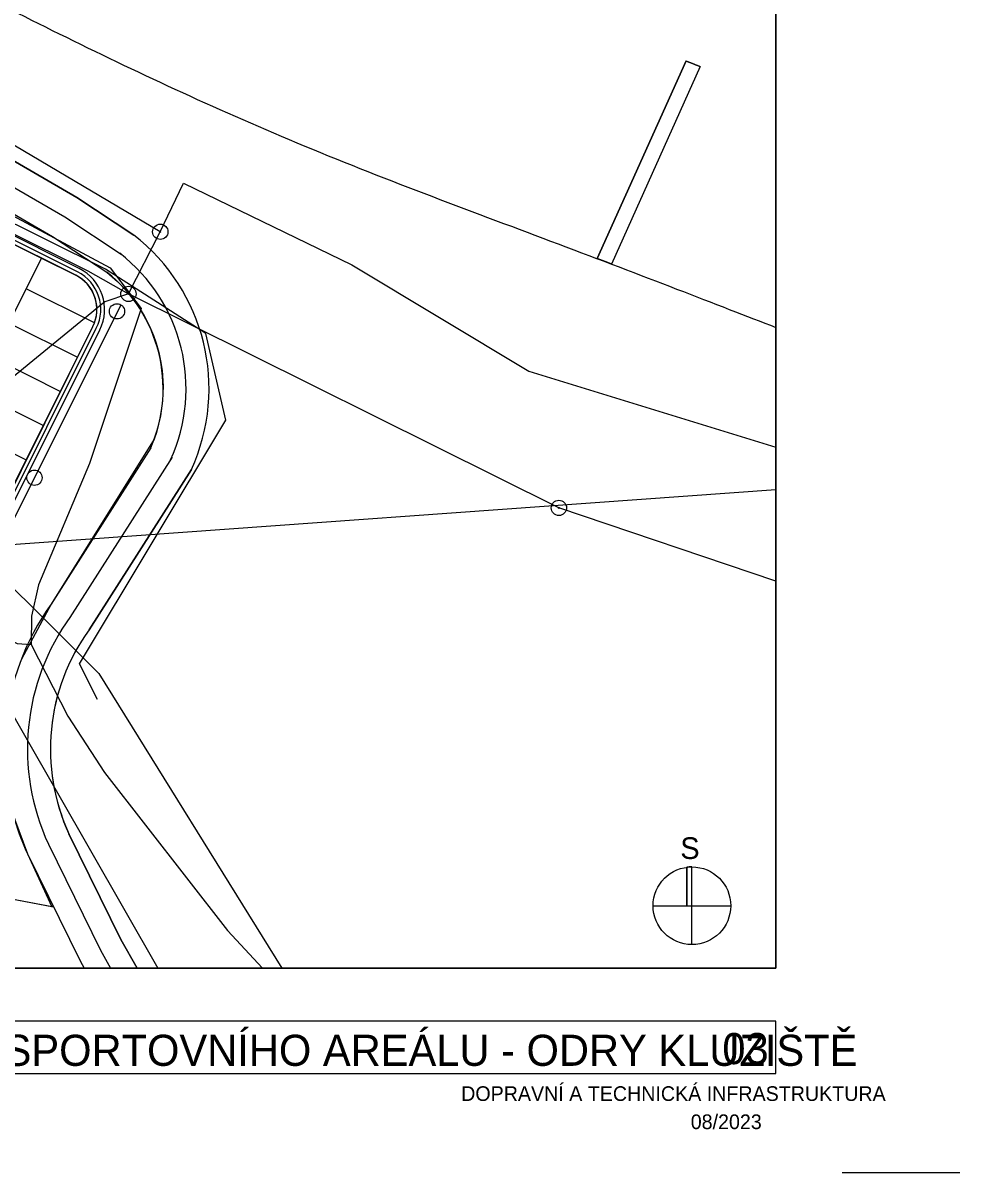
# Model space of a CAD drawing. Extents: x -504998 to -504814, y -1117353 to -1117234.
# Drawn here: x -504875.4 to -504814.1, y -1117352.8 to -1117277.6 of the extents above; entities that cross this region are included whole.
import ezdxf

# ---------------------------------------------------------------- set-up
doc = ezdxf.new("R2010")
doc.units = 0
for name, color, linetype in [('01_OPLOCENI', 7, 'Continuous'), ('01_ST tenká', 7, 'Continuous'), ('02_PL_PARKOVISTE', 7, 'Continuous'), ('03_razitko', 7, 'Continuous'), ('03_SEVERKA', 7, 'Continuous'), ('_01_CYKLOSTEZKA', 7, 'Continuous'), ('_01_kanalizace', 7, 'Continuous'), ('_01_vedeni_NN_nadzemni', 7, 'Continuous'), ('_01_vedeni_VN_podzemni', 7, 'Continuous'), ('_01_vedeni_VN_podzemni_NAVRH', 7, 'Continuous'), ('_01_VO', 7, 'Continuous'), ('_01_vodovod_pripojky', 7, 'Continuous'), ('_02_pl_ cesta', 7, 'Continuous'), ('ADJUST', 7, 'Continuous'), ('D_mobiliar_popis', 7, 'Continuous'), ('Hranice parcel', 7, 'Continuous'), ('pop-ram-popis', 7, 'Continuous'), ('res_uzemi', 7, 'Continuous')]:
    doc.layers.add(name, color=color, linetype=linetype)

msp = doc.modelspace()

# ---------------------------------------------------------------- linework, layer by layer
at = {"layer": '01_OPLOCENI'}
for p, q in [((-504871.811, -1117293.907), (-504902.037, -1117278.798)), ((-504879.295, -1117315.03), (-504870.581, -1117297.597))]:
    msp.add_line(p, q, dxfattribs=at)
msp.add_arc((-504873.04, -1117296.367), 2.75, 333.44015, 63.44015, dxfattribs=at)
at = {"layer": '01_ST tenká'}
for p, q in [((-504871.699, -1117293.684), (-504900.842, -1117279.115)), ((-504832.037, -1117280.116), (-504837.848, -1117293.043)), ((-504837.848, -1117293.043), (-504832.037, -1117280.116)), ((-504871.923, -1117294.131), (-504899.187, -1117280.502)), ((-504831.108, -1117280.488), (-504836.911, -1117293.399)), ((-504831.108, -1117280.488), (-504836.911, -1117293.399)), ((-504876.278, -1117297.252), (-504871.806, -1117299.488)), ((-504879.407, -1117314.694), (-504870.804, -1117297.485)), ((-504879.183, -1117315.365), (-504870.357, -1117297.708)), ((-504877.396, -1117299.489), (-504872.923, -1117301.724)), ((-504878.514, -1117301.725), (-504874.041, -1117303.96)), ((-504879.631, -1117303.961), (-504875.159, -1117306.197))]:
    msp.add_line(p, q, dxfattribs=at)
for points in [[(-504885.563, -1117293.461), (-504876.618, -1117297.933), (-504874.159, -1117293.013), (-504883.103, -1117288.542)], [(-504874.159, -1117293.013), (-504876.618, -1117297.933), (-504885.563, -1117293.461), (-504883.103, -1117288.542)]]:
    msp.add_lwpolyline(points, close=True, dxfattribs=at)
for radius in [2.5, 3]:
    msp.add_arc((-504873.04, -1117296.367), radius, 333.44015, 63.44015, dxfattribs=at)
for points, degree in [([(-504884.688, -1117272.271), (-504882.067, -1117273.747), (-504872.833, -1117278.571), (-504857.22, -1117285.84), (-504840.071, -1117292.154), (-504829.913, -1117296.084), (-504826.17, -1117297.542)], 3), ([(-504832.037, -1117280.116), (-504831.727, -1117280.239), (-504831.417, -1117280.363), (-504831.108, -1117280.488)], 2), ([(-504837.417, -1117293.207), (-504837.56, -1117293.153), (-504837.704, -1117293.098), (-504837.848, -1117293.043)], 2), ([(-504836.911, -1117293.399), (-504837.08, -1117293.335), (-504837.248, -1117293.271), (-504837.417, -1117293.207)], 2)]:
    msp.add_open_spline(points, degree=degree, dxfattribs=at)
at = {"layer": '02_PL_PARKOVISTE'}
msp.add_lwpolyline([(-504870.7, -1117297.246), (-504875.158, -1117295.017), (-504875.158, -1117295.017), (-504875.16, -1117295.016), (-504874.159, -1117293.013), (-504871.923, -1117294.131)], dxfattribs=at)
msp.add_lwpolyline([(-504881.867, -1117308.433), (-504877.409, -1117310.663), (-504870.804, -1117297.485), (-504870.738, -1117297.341), (-504870.7, -1117297.246), (-504875.158, -1117295.017), (-504876.618, -1117297.933)], close=True, dxfattribs=at)
msp.add_arc((-504873.04, -1117296.367), 2.5, 339.41795, 63.44015, dxfattribs=at)
at = {"layer": '03_SEVERKA'}
for p, q in [((-504831.995, -1117335.347), (-504831.995, -1117332.832)), ((-504831.995, -1117335.347), (-504831.995, -1117332.832)), ((-504831.995, -1117335.347), (-504831.995, -1117332.832)), ((-504831.995, -1117335.347), (-504831.995, -1117332.832)), ((-504831.657, -1117337.885), (-504831.657, -1117332.809)), ((-504831.657, -1117337.885), (-504831.657, -1117332.809)), ((-504831.657, -1117337.885), (-504831.657, -1117332.809)), ((-504831.657, -1117337.885), (-504831.657, -1117332.809)), ((-504834.195, -1117335.347), (-504829.119, -1117335.347)), ((-504834.195, -1117335.347), (-504829.119, -1117335.347)), ((-504834.195, -1117335.347), (-504829.119, -1117335.347)), ((-504834.195, -1117335.347), (-504829.119, -1117335.347))]:
    msp.add_line(p, q, dxfattribs=at)
msp.add_lwpolyline([(-504831.995, -1117332.832), (-504831.995, -1117335.347), (-504831.657, -1117335.347), (-504831.657, -1117332.809)], dxfattribs=at)
msp.add_lwpolyline([(-504831.995, -1117332.832), (-504831.995, -1117335.347), (-504831.657, -1117335.347), (-504831.657, -1117332.809)], dxfattribs=at)
msp.add_lwpolyline([(-504831.995, -1117332.832), (-504831.995, -1117335.347), (-504831.657, -1117335.347), (-504831.657, -1117332.809)], dxfattribs=at)
msp.add_lwpolyline([(-504831.995, -1117332.832), (-504831.995, -1117335.347), (-504831.657, -1117335.347), (-504831.657, -1117332.809)], dxfattribs=at)
msp.add_circle((-504831.657, -1117335.347), 2.538, dxfattribs=at)
msp.add_circle((-504831.657, -1117335.347), 2.538, dxfattribs=at)
msp.add_circle((-504831.657, -1117335.347), 2.538, dxfattribs=at)
msp.add_circle((-504831.657, -1117335.347), 2.538, dxfattribs=at)
msp.add_arc((-504831.657, -1117335.347), 2.538, 90, 97.66111, dxfattribs=at)
msp.add_arc((-504831.657, -1117335.347), 2.538, 90, 97.66111, dxfattribs=at)
msp.add_arc((-504831.657, -1117335.347), 2.538, 90, 97.66111, dxfattribs=at)
msp.add_arc((-504831.657, -1117335.347), 2.538, 90, 97.66111, dxfattribs=at)
at = {"layer": '_01_CYKLOSTEZKA'}
for p, q in [((-504865.634, -1117306.026), (-504872.317, -1117316.507)), ((-504873.358, -1117335.449), (-504877.875, -1117334.582))]:
    msp.add_line(p, q, dxfattribs=at)
for points in [[(-504949.925, -1117237.019), (-504941.567, -1117243.159), (-504910.25, -1117266.718), (-504900.416, -1117273.69), (-504892.095, -1117278.885), (-504882.931, -1117284.355), (-504872.646, -1117290.318), (-504868.959, -1117292.751)], [(-504947.392, -1117237.019), (-504940.672, -1117241.955), (-504909.365, -1117265.506), (-504899.585, -1117272.441), (-504891.313, -1117277.605), (-504882.171, -1117283.062), (-504871.856, -1117289.042), (-504868.133, -1117291.499)], [(-504951.877, -1117237.447), (-504942.462, -1117244.362), (-504925.185, -1117257.359), (-504911.135, -1117267.929), (-504901.248, -1117274.939), (-504892.877, -1117280.166), (-504883.692, -1117285.648), (-504873.436, -1117291.594), (-504869.888, -1117293.936)], [(-504867.018, -1117305.406), (-504868.551, -1117307.811), (-504869.749, -1117309.689), (-504873.536, -1117315.628)], [(-504864.369, -1117306.832), (-504871.052, -1117317.313)], [(-504872.368, -1117330.655), (-504868.988, -1117337.546), (-504867.914, -1117339.419)], [(-504875.077, -1117331.944), (-504871.638, -1117338.954), (-504871.372, -1117339.419)], [(-504873.715, -1117331.316), (-504870.313, -1117338.25), (-504869.643, -1117339.419)]]:
    msp.add_lwpolyline(points, dxfattribs=at)
for centre, radius, start, end in [((-504875.92, -1117301.539), 12.705, 335.38077, 52.20502), ((-504875.92, -1117301.539), 11.205, 335.38077, 52.20502), ((-504875.92, -1117301.539), 9.705, 336.52234, 51.5751), ((-504860.302, -1117325.11), 16.28, 144.38158, 204.8235), ((-504860.302, -1117325.11), 14.78, 144.04957, 204.8235), ((-504860.302, -1117325.11), 13.28, 144.04957, 204.8235)]:
    msp.add_arc(centre, radius, start, end, dxfattribs=at)
at = {"layer": '_01_kanalizace'}
msp.add_lwpolyline([(-504946.836, -1117237.019), (-504933.671, -1117256.588), (-504926.695, -1117266.535), (-504900.105, -1117290.54), (-504870.414, -1117320.168), (-504858.46, -1117339.419)], dxfattribs=at)
msp.add_lwpolyline([(-504946.836, -1117237.019), (-504933.671, -1117256.588), (-504926.695, -1117266.535), (-504900.105, -1117290.54), (-504870.414, -1117320.168), (-504858.46, -1117339.419)], dxfattribs=at)
at = {"layer": '_01_vedeni_NN_nadzemni'}
msp.add_lwpolyline([(-504870.495, -1117321.873), (-504871.684, -1117319.525), (-504862.111, -1117303.6), (-504863.422, -1117297.934), (-504869.983, -1117293.727), (-504893.402, -1117282.088), (-504903.748, -1117276.945), (-504931.417, -1117254.947), (-504949.935, -1117241.128), (-504957.339, -1117248.262), (-504960.704, -1117246.616)], dxfattribs=at)
msp.add_lwpolyline([(-504870.495, -1117321.873), (-504871.684, -1117319.525), (-504862.111, -1117303.6), (-504863.422, -1117297.934), (-504869.983, -1117293.727), (-504893.402, -1117282.088), (-504903.748, -1117276.945), (-504931.417, -1117254.947), (-504949.935, -1117241.128), (-504957.339, -1117248.262), (-504960.704, -1117246.616)], dxfattribs=at)
at = {"layer": '_01_vedeni_VN_podzemni'}
msp.add_lwpolyline([(-504967.686, -1117264.27), (-504958.416, -1117247.487), (-504954.85, -1117243.33), (-504950.18, -1117242.588), (-504946.511, -1117244.382), (-504935.944, -1117252.201), (-504915.723, -1117266.72), (-504902.782, -1117276.696), (-504878.838, -1117288.739), (-504869.669, -1117293.64), (-504867.647, -1117296.302), (-504871.022, -1117306.429), (-504874.354, -1117314.377), (-504874.816, -1117316.413), (-504874.843, -1117318.266), (-504872.437, -1117322.953), (-504870.053, -1117326.638), (-504862.009, -1117336.965), (-504859.73, -1117339.419)], dxfattribs=at)
msp.add_lwpolyline([(-504967.686, -1117264.27), (-504958.416, -1117247.487), (-504954.85, -1117243.33), (-504950.18, -1117242.588), (-504946.511, -1117244.382), (-504935.944, -1117252.201), (-504915.723, -1117266.72), (-504902.782, -1117276.696), (-504878.838, -1117288.739), (-504869.669, -1117293.64), (-504867.647, -1117296.302), (-504871.022, -1117306.429), (-504874.354, -1117314.377), (-504874.816, -1117316.413), (-504874.843, -1117318.266), (-504872.437, -1117322.953), (-504870.053, -1117326.638), (-504862.009, -1117336.965), (-504859.73, -1117339.419)], dxfattribs=at)
at = {"layer": '_01_vedeni_VN_podzemni_NAVRH'}
msp.add_lwpolyline([(-504894.87, -1117308.629), (-504875.755, -1117318.2), (-504874.843, -1117318.266)], dxfattribs=at)
msp.add_lwpolyline([(-504894.87, -1117308.629), (-504875.755, -1117318.2), (-504874.843, -1117318.266)], dxfattribs=at)
at = {"layer": '_01_VO'}
msp.add_line((-504868.974, -1117296.06), (-504879.34, -1117316.797), dxfattribs=at)
msp.add_line((-504868.974, -1117296.06), (-504879.34, -1117316.797), dxfattribs=at)
for centre in [(-504869.23, -1117296.49), (-504869.23, -1117296.49), (-504874.625, -1117307.364), (-504874.625, -1117307.364)]:
    msp.add_circle(centre, 0.5, dxfattribs=at)
at = {"layer": '_01_vodovod_pripojky'}
msp.add_line((-504826.17, -1117308.151), (-504890.193, -1117312.767), dxfattribs=at)
msp.add_line((-504826.17, -1117308.151), (-504890.193, -1117312.767), dxfattribs=at)
at = {"layer": '_02_pl_ cesta'}
for p, q in [((-504867.018, -1117305.406), (-504873.536, -1117315.628)), ((-504871.052, -1117317.313), (-504864.369, -1117306.832))]:
    msp.add_line(p, q, dxfattribs=at)
for points in [[(-504868.133, -1117291.499), (-504871.856, -1117289.042), (-504882.171, -1117283.062), (-504891.313, -1117277.605), (-504899.585, -1117272.441), (-504909.365, -1117265.506), (-504940.672, -1117241.955), (-504947.392, -1117237.019), (-504951.453, -1117237.019)], [(-504951.877, -1117237.447), (-504942.462, -1117244.362), (-504911.135, -1117267.929), (-504901.248, -1117274.939), (-504892.877, -1117280.166), (-504883.692, -1117285.648), (-504873.436, -1117291.594), (-504869.888, -1117293.936)], [(-504875.077, -1117331.944), (-504873.391, -1117335.381), (-504873.484, -1117335.425), (-504877.875, -1117334.582), (-504882.286, -1117326.394), (-504880.59, -1117322.011), (-504879.576, -1117323.766), (-504878.975, -1117323.993), (-504876.032, -1117329.304)], [(-504875.077, -1117331.944), (-504871.638, -1117338.954), (-504871.372, -1117339.419), (-504867.914, -1117339.419), (-504868.988, -1117337.546), (-504872.368, -1117330.655)]]:
    msp.add_lwpolyline(points, dxfattribs=at)
for centre, radius, start, end in [((-504875.92, -1117301.539), 12.705, 335.38077, 52.20502), ((-504875.92, -1117301.539), 9.705, 336.52234, 51.5751), ((-504860.302, -1117325.11), 16.28, 144.38158, 204.8235), ((-504860.302, -1117325.11), 13.28, 144.04957, 204.68325), ((-504860.302, -1117325.11), 16.28, 194.92932, 204.8235)]:
    msp.add_arc(centre, radius, start, end, dxfattribs=at)
at = {"layer": 'ADJUST'}
msp.add_lwpolyline([(-504972.808, -1117346.312), (-504826.17, -1117346.312), (-504826.17, -1117342.894), (-504972.808, -1117342.894)], close=True, dxfattribs=at)
at = {"layer": 'Hranice parcel'}
for p, q in [((-504866.4, -1117291.29), (-504899.17, -1117271.91)), ((-504866.4, -1117291.29), (-504864.88, -1117288.11)), ((-504868.48, -1117295.35), (-504866.4, -1117291.29)), ((-504871.14, -1117293.84), (-504868.48, -1117295.35))]:
    msp.add_line(p, q, dxfattribs=at)
for points in [[(-504975.87, -1117280.95), (-504958.75, -1117250.3), (-504881.88, -1117288.5), (-504871.14, -1117293.84)], [(-504864.88, -1117288.11), (-504853.88, -1117293.44), (-504842.31, -1117300.4), (-504826.17, -1117305.364)], [(-504868.48, -1117295.35), (-504870.02, -1117295.86), (-504884.54, -1117307.74)], [(-504826.17, -1117314.119), (-504840.35, -1117309.34), (-504868.48, -1117295.35)], [(-504884.54, -1117307.74), (-504884.4, -1117307.99), (-504881.95, -1117312.58), (-504866.555, -1117339.419)]]:
    msp.add_lwpolyline(points, dxfattribs=at)
for centre, radius in [((-504866.4, -1117291.29), 0.5), ((-504866.4, -1117291.29), 0.0303), ((-504868.48, -1117295.35), 0.5), ((-504868.48, -1117295.35), 0.0303), ((-504840.35, -1117309.34), 0.5), ((-504840.35, -1117309.34), 0.0303)]:
    msp.add_circle(centre, radius, dxfattribs=at)
at = {"layer": 'pop-ram-popis'}
msp.add_line((-504814.135, -1117352.819), (-504821.829, -1117352.819), dxfattribs=at)
for points in [[(-504985.829, -1117237.019), (-504826.17, -1117237.019), (-504826.17, -1117339.419), (-504985.829, -1117339.419)], [(-504826.17, -1117339.419), (-504826.17, -1117273.019), (-504874.17, -1117273.019), (-504874.17, -1117237.019), (-504985.829, -1117237.019), (-504985.829, -1117339.419)], [(-504826.17, -1117339.419), (-504826.17, -1117237.019), (-504985.829, -1117237.019), (-504985.829, -1117339.419)], [(-504826.17, -1117273.019), (-504874.17, -1117273.019), (-504874.17, -1117237.019), (-504985.829, -1117237.019), (-504985.829, -1117339.419), (-504826.17, -1117339.419)]]:
    msp.add_lwpolyline(points, close=True, dxfattribs=at)
at = {"layer": 'res_uzemi'}
for points in [[(-504881.128, -1117287.134), (-504873.436, -1117291.594), (-504869.888, -1117293.936), (-504869.191, -1117294.545), (-504868.616, -1117295.147), (-504868.137, -1117295.741), (-504867.763, -1117296.28), (-504867.591, -1117296.556), (-504867.462, -1117296.778), (-504867.257, -1117297.163), (-504867.049, -1117297.601), (-504866.854, -1117298.073), (-504866.679, -1117298.573), (-504866.504, -1117299.183), (-504866.364, -1117299.839), (-504866.285, -1117300.366), (-504866.215, -1117301.387), (-504866.247, -1117302.337), (-504866.379, -1117303.319), (-504866.65, -1117304.416), (-504866.795, -1117304.845), (-504873.536, -1117315.628), (-504875.48, -1117319.222)], [(-504875.93, -1117329.67), (-504875.077, -1117331.944), (-504873.484, -1117335.425), (-504877.875, -1117334.582)]]:
    msp.add_lwpolyline(points, dxfattribs=at)

# ---------------------------------------------------------------- texts
at = {"layer": '03_razitko'}
for s, height, p in [('STUDIE SPORTOVNÍHO AREÁLU - ODRY KLUZIŠTĚ', 2.03512, (-504887.375, -1117345.815)), ('DOPRAVNÍ A TECHNICKÁ INFRASTRUKTURA', 0.96, (-504846.736, -1117348.109)), ('08/2023', 0.96, (-504831.732, -1117349.951))]:
    msp.add_text(s, height=height, rotation=360, dxfattribs=at).set_placement(p)
at = {"layer": '03_SEVERKA'}
msp.add_text('S', height=1.42, rotation=359.73244, dxfattribs=at).set_placement((-504832.42, -1117332.289))
msp.add_text('S', height=1.42, rotation=359.73244, dxfattribs=at).set_placement((-504832.42, -1117332.289))
msp.add_text('S', height=1.42, rotation=359.73244, dxfattribs=at).set_placement((-504832.42, -1117332.289))
msp.add_text('S', height=1.42, rotation=359.73244, dxfattribs=at).set_placement((-504832.42, -1117332.289))
at = {"layer": 'D_mobiliar_popis'}
msp.add_text('03', height=2.0351, rotation=360, dxfattribs=at).set_placement((-504829.667, -1117345.704))

doc.saveas('drawing.dxf')
